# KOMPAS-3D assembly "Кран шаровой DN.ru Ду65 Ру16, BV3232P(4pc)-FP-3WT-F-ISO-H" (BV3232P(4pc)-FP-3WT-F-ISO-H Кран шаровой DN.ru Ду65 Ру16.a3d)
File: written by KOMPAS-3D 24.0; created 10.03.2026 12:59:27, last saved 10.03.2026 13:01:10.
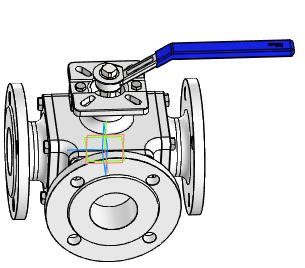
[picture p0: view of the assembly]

Document properties: Автор: R2D2; Полное имя файла: E:\Работа\Зайцев\BV3232P(4pc)-FP-3WT-F-ISO-H Кран шаровой DN.ru Ду15-100 Ру16\DN65\исходные материалы\BV3232P(4pc)-FP-3WT-F-ISO-H Кран шаровой DN.ru Ду65 Ру16.a3d

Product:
- Component [assembly]: Сборка1  | qty 1  | pos. 1  | Масса: 31.82202; Автор: R2D2; source file: dn65_3d_step.a3d
- Part/product: Кран шаровой DN.ru Ду65 Ру16  | designation BV3232P(4pc)-FP-3WT-F-ISO-H
    Масса: 26.5
    Раздел спецификации: Прочие изделия
    Примечание: D160-36352

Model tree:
1. Эскиз:1  (labels: Грань.Твердое тело1; Ребро.Твердое тело1)
2. Элемент выдавливания:1  (labels: Грань.Твердое тело1; Твердое тело1)
     Расстояние 2 = 0.01

Referenced files in E:\Работа\Зайцев\BV3232P(4pc)-FP-3WT-F-ISO-H Кран шаровой DN.ru Ду15-100 Ру16\DN65\исходные материалы\: dn65_3d_step.a3d
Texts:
  BV3232P(4pc)-FP-3WT-F-ISO-H
  Сборка1 Сборка1
  Ось Z.Начало координат
  Ось Y.Начало координат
